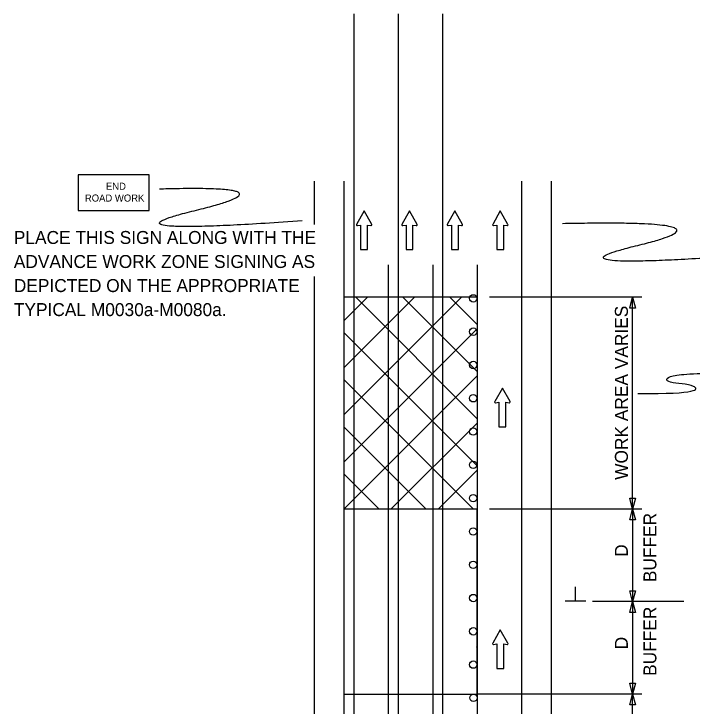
# Model space of a CAD drawing. Extents: x 16727 to 18475, y 5704 to 7011.
# Drawn here: x 16733.5 to 17100, y 6636.8 to 7011.1 of the extents above; entities that cross this region are included whole.
import ezdxf

# ---------------------------------------------------------------- set-up
doc = ezdxf.new("R2010")
doc.units = 0
for name, color, linetype in [('ALI_LEGAL_EX', 7, 'Continuous'), ('MT_SCRATCH_LEVEL_A', 7, 'Continuous'), ('MT_SCRATCH_LEVEL_E', 7, 'Continuous'), ('PAVT_EDGE_EX', 7, 'Continuous'), ('TRAFFIC_SIGNS_PR', 7, 'Continuous'), ('TYPICAL_TEXT_DIMEN_PR', 7, 'Continuous')]:
    doc.layers.add(name, color=color, linetype=linetype)

msp = doc.modelspace()

# ---------------------------------------------------------------- linework, layer by layer
at = {"layer": 'ALI_LEGAL_EX'}
for p, q in [((16917.23, 7011.11), (16917.23, 6181.92)), ((16941.23, 7011.11), (16941.23, 6181.92)), ((16965.23, 7011.11), (16965.23, 6181.92)), ((16965.23, 7011.11), (16965.23, 6181.92)), ((16935.85, 6875.49), (16935.85, 6046.3)), ((16959.85, 6875.49), (16959.85, 6046.3)), ((16983.85, 6875.49), (16983.85, 6046.3)), ((16983.85, 6875.49), (16983.85, 6046.3))]:
    msp.add_line(p, q, dxfattribs=at)
for points in [[(16935.85, 6875.49), (16935.85, 6850.49)], [(16959.85, 6875.49), (16959.85, 6850.49)], [(16983.85, 6875.49), (16983.85, 6850.49)], [(16935.85, 6775.49), (16935.85, 6750.49)], [(16959.85, 6775.49), (16959.85, 6750.49)], [(16983.85, 6775.49), (16983.85, 6750.49)], [(16935.85, 6675.49), (16935.85, 6650.49)], [(16959.85, 6675.49), (16959.85, 6650.49)], [(16983.85, 6675.49), (16983.85, 6650.49)]]:
    msp.add_lwpolyline(points, dxfattribs=at)
at = {"layer": 'MT_SCRATCH_LEVEL_A'}
for p, q in [((16911.85, 6845.15), (16924.57, 6857.87)), ((16911.85, 6819.7), (16950.02, 6857.87)), ((16911.85, 6794.24), (16975.48, 6857.87)), ((16983.85, 6857.87), (16911.85, 6857.87)), ((16983.85, 6792.25), (16918.23, 6857.87)), ((16983.85, 6817.7), (16943.69, 6857.87)), ((16983.85, 6843.16), (16969.15, 6857.87)), ((16911.85, 6768.79), (16983.85, 6840.79)), ((16983.85, 6766.79), (16911.85, 6838.79)), ((16911.85, 6743.33), (16983.85, 6815.33)), ((16981.86, 6743.33), (16911.85, 6813.34)), ((16937.31, 6743.33), (16983.85, 6789.88)), ((16956.4, 6743.33), (16911.85, 6787.88)), ((16911.85, 6787.3), (16911.85, 6643.33)), ((16911.85, 6787.3), (16911.85, 6672.76)), ((16962.77, 6743.33), (16983.85, 6764.42)), ((16930.95, 6743.33), (16911.85, 6762.42)), ((16983.85, 6743.33), (16911.85, 6743.33)), ((16911.85, 6672.76), (16911.85, 6643.33)), ((16983.76, 6671.57), (16983.81, 6671.49)), ((16983.56, 6668.93), (16983.57, 6668.81))]:
    msp.add_line(p, q, dxfattribs=at)
at = {"layer": 'MT_SCRATCH_LEVEL_E'}
for p, q in [((16922.76, 6904.53), (16918.65, 6897.29)), ((16922.76, 6904.53), (16918.65, 6897.29)), ((16926.91, 6897.29), (16922.76, 6904.53)), ((16926.91, 6897.29), (16922.76, 6904.53)), ((16947.29, 6904.53), (16943.18, 6897.29)), ((16947.29, 6904.53), (16943.18, 6897.29)), ((16951.44, 6897.29), (16947.29, 6904.53)), ((16951.44, 6897.29), (16947.29, 6904.53)), ((16971.82, 6904.53), (16967.71, 6897.29)), ((16971.82, 6904.53), (16967.71, 6897.29)), ((16975.97, 6897.29), (16971.82, 6904.53)), ((16975.97, 6897.29), (16971.82, 6904.53)), ((16996.38, 6904.53), (16992.27, 6897.29)), ((16996.38, 6904.53), (16992.27, 6897.29)), ((17000.53, 6897.29), (16996.38, 6904.53)), ((17000.53, 6897.29), (16996.38, 6904.53)), ((16919.14, 6896.61), (16920.91, 6896.93)), ((16919.14, 6896.61), (16920.91, 6896.93)), ((16920.91, 6896.93), (16920.91, 6883.67)), ((16920.91, 6896.93), (16920.91, 6883.67)), ((16924.65, 6883.67), (16924.65, 6896.93)), ((16924.65, 6896.93), (16926.43, 6896.61)), ((16924.65, 6883.67), (16924.65, 6896.93)), ((16924.65, 6896.93), (16926.43, 6896.61)), ((16943.67, 6896.61), (16945.44, 6896.93)), ((16943.67, 6896.61), (16945.44, 6896.93)), ((16945.44, 6896.93), (16945.44, 6883.67)), ((16945.44, 6896.93), (16945.44, 6883.67)), ((16949.18, 6883.67), (16949.18, 6896.93)), ((16949.18, 6896.93), (16950.96, 6896.61)), ((16949.18, 6883.67), (16949.18, 6896.93)), ((16949.18, 6896.93), (16950.96, 6896.61)), ((16968.19, 6896.61), (16969.97, 6896.93)), ((16968.19, 6896.61), (16969.97, 6896.93)), ((16969.97, 6896.93), (16969.97, 6883.67)), ((16969.97, 6896.93), (16969.97, 6883.67)), ((16973.71, 6883.67), (16973.71, 6896.93)), ((16973.71, 6896.93), (16975.49, 6896.61)), ((16973.71, 6883.67), (16973.71, 6896.93)), ((16973.71, 6896.93), (16975.49, 6896.61)), ((16992.75, 6896.61), (16994.53, 6896.93)), ((16992.75, 6896.61), (16994.53, 6896.93)), ((16994.53, 6896.93), (16994.53, 6883.67)), ((16994.53, 6896.93), (16994.53, 6883.67)), ((16998.27, 6883.67), (16998.27, 6896.93)), ((16998.27, 6896.93), (17000.05, 6896.61)), ((16998.27, 6883.67), (16998.27, 6896.93)), ((16998.27, 6896.93), (17000.05, 6896.61)), ((16920.91, 6883.67), (16924.65, 6883.67)), ((16920.91, 6883.67), (16924.65, 6883.67)), ((16945.44, 6883.67), (16949.18, 6883.67)), ((16945.44, 6883.67), (16949.18, 6883.67)), ((16969.97, 6883.67), (16973.71, 6883.67)), ((16969.97, 6883.67), (16973.71, 6883.67)), ((16994.53, 6883.67), (16998.27, 6883.67)), ((16994.53, 6883.67), (16998.27, 6883.67)), ((16997.48, 6808.78), (16993.37, 6801.54)), ((16997.48, 6808.78), (16993.37, 6801.54)), ((17001.63, 6801.54), (16997.48, 6808.78)), ((17001.63, 6801.54), (16997.48, 6808.78)), ((16993.85, 6800.85), (16995.63, 6801.17)), ((16993.85, 6800.85), (16995.63, 6801.17)), ((16995.63, 6801.17), (16995.63, 6787.91)), ((16995.63, 6801.17), (16995.63, 6787.91)), ((16999.37, 6787.91), (16999.37, 6801.17)), ((16999.37, 6801.17), (17001.15, 6800.85)), ((16999.37, 6787.91), (16999.37, 6801.17)), ((16999.37, 6801.17), (17001.15, 6800.85)), ((16995.63, 6787.91), (16999.37, 6787.91)), ((16995.63, 6787.91), (16999.37, 6787.91)), ((16996.38, 6678.13), (16992.27, 6670.89)), ((16996.38, 6678.13), (16992.27, 6670.89)), ((17000.53, 6670.89), (16996.38, 6678.13)), ((17000.53, 6670.89), (16996.38, 6678.13)), ((16992.75, 6670.2), (16994.53, 6670.52)), ((16992.75, 6670.2), (16994.53, 6670.52)), ((16994.53, 6670.52), (16994.53, 6657.26)), ((16994.53, 6670.52), (16994.53, 6657.26)), ((16998.27, 6657.26), (16998.27, 6670.52)), ((16998.27, 6670.52), (17000.05, 6670.2)), ((16998.27, 6657.26), (16998.27, 6670.52)), ((16998.27, 6670.52), (17000.05, 6670.2)), ((16994.53, 6657.26), (16998.27, 6657.26)), ((16994.53, 6657.26), (16998.27, 6657.26))]:
    msp.add_line(p, q, dxfattribs=at)
for centre, start, end in [((16919.06, 6897.07), 150.4248, 279.9638), ((16919.06, 6897.07), 150.4248, 279.9638), ((16926.5, 6897.07), 260.0362, 29.7731), ((16926.5, 6897.07), 260.0362, 29.7731), ((16943.59, 6897.07), 150.4248, 279.9638), ((16943.59, 6897.07), 150.4248, 279.9638), ((16951.03, 6897.07), 260.0362, 29.7731), ((16951.03, 6897.07), 260.0362, 29.7731), ((16968.12, 6897.07), 150.4248, 279.9638), ((16968.12, 6897.07), 150.4248, 279.9638), ((16975.56, 6897.07), 260.0362, 29.7731), ((16975.56, 6897.07), 260.0362, 29.7731), ((16992.68, 6897.07), 150.4248, 279.9638), ((16992.68, 6897.07), 150.4248, 279.9638), ((17000.12, 6897.07), 260.0362, 29.7731), ((17000.12, 6897.07), 260.0362, 29.7731), ((16993.78, 6801.31), 150.4248, 279.9638), ((16993.78, 6801.31), 150.4248, 279.9638), ((17001.22, 6801.31), 260.0362, 29.7731), ((17001.22, 6801.31), 260.0362, 29.7731), ((16992.68, 6670.66), 150.4248, 279.9638), ((16992.68, 6670.66), 150.4248, 279.9638), ((17000.12, 6670.66), 260.0362, 29.7731), ((17000.12, 6670.66), 260.0362, 29.7731)]:
    msp.add_arc(centre, 0.463, start, end, dxfattribs=at)
at = {"layer": 'PAVT_EDGE_EX'}
for p, q in [((16895.85, 6920.73), (16895.85, 6897.26)), ((16911.85, 6920.73), (16911.85, 6024.13)), ((17007.85, 6920.73), (17007.85, 6024.13)), ((17023.85, 6920.73), (17023.85, 6024.13)), ((16895.85, 6869.12), (16895.85, 6024.13))]:
    msp.add_line(p, q, dxfattribs=at)
msp.add_lwpolyline([(16983.85, 6743.33), (16911.85, 6743.33), (16911.85, 6643.33), (16983.85, 6643.33)], close=True, dxfattribs=at)
at = {"layer": 'TRAFFIC_SIGNS_PR'}
msp.add_lwpolyline([(16768.29, 6904.86), (16806.69, 6904.86), (16806.69, 6924.06), (16768.29, 6924.06)], close=True, dxfattribs=at)
for centre in [(16981.76, 6857.28), (16981.76, 6839.28), (16981.76, 6821.28), (16981.76, 6803.28), (16981.76, 6785.28), (16981.76, 6767.28), (16981.76, 6749.28), (16981.76, 6731.28), (16981.76, 6713.28), (16981.76, 6695.28), (16981.76, 6677.28), (16981.76, 6659.28), (16981.85, 6641.33), (16981.85, 6641.33)]:
    msp.add_circle(centre, 2, dxfattribs=at)
for points in [[(16889.36, 6899.17), (16774.14, 6890.93), (16888.05, 6918.52), (16812.21, 6916.35)], [(17129.18, 6880.47), (17013.95, 6872.23), (17127.86, 6899.81), (17029.92, 6897.64)]]:
    msp.add_open_spline(points, degree=2, dxfattribs=at)
at = {"layer": 'TYPICAL_TEXT_DIMEN_PR'}
for p, q in [((17072.85, 6857.87), (16990.46, 6857.87)), ((17066.28, 6852.01), (17067.85, 6857.87)), ((17067.85, 6743.33), (17067.85, 6857.87)), ((17067.85, 6857.87), (17069.42, 6852.01)), ((17067.85, 6852.01), (17066.28, 6852.01)), ((17069.42, 6852.01), (17067.85, 6852.01)), ((17067.85, 6743.33), (17066.28, 6749.19)), ((17066.28, 6749.19), (17067.85, 6749.19)), ((17067.85, 6749.19), (17069.42, 6749.19)), ((17069.42, 6749.19), (17067.85, 6743.33)), ((17072.85, 6743.33), (16990.46, 6743.33)), ((17072.85, 6743.33), (16990.46, 6743.33)), ((17066.28, 6737.47), (17067.85, 6743.33)), ((17067.85, 6743.33), (17067.85, 6693.33)), ((17067.85, 6743.33), (17069.42, 6737.47)), ((17067.85, 6737.47), (17066.28, 6737.47)), ((17069.42, 6737.47), (17067.85, 6737.47)), ((17036.98, 6693.52), (17036.98, 6701.31)), ((17067.85, 6693.33), (17066.28, 6699.19)), ((17066.28, 6699.19), (17067.85, 6699.19)), ((17067.85, 6699.19), (17069.42, 6699.19)), ((17069.42, 6699.19), (17067.85, 6693.33)), ((17042.6, 6693.52), (17031.35, 6693.52)), ((17095.51, 6693.33), (17046.27, 6693.33)), ((17066.28, 6687.47), (17067.85, 6693.33)), ((17067.85, 6693.33), (17067.85, 6643.33)), ((17067.85, 6693.33), (17069.42, 6687.47)), ((17067.85, 6687.47), (17066.28, 6687.47)), ((17069.42, 6687.47), (17067.85, 6687.47)), ((17067.85, 6643.33), (17066.28, 6649.19)), ((17066.28, 6649.19), (17067.85, 6649.19)), ((17067.85, 6649.19), (17069.42, 6649.19)), ((17069.42, 6649.19), (17067.85, 6643.33)), ((17072.85, 6643.33), (16983.85, 6643.33)), ((17066.28, 6637.47), (17067.85, 6643.33)), ((17067.85, 6612.77), (17067.85, 6643.33)), ((17067.85, 6643.33), (17069.42, 6637.47)), ((17067.85, 6637.47), (17066.28, 6637.47)), ((17069.42, 6637.47), (17067.85, 6637.47))]:
    msp.add_line(p, q, dxfattribs=at)
msp.add_open_spline([(17070.66, 6805.93), (17103.88, 6805.42), (17103.88, 6811.13), (17085.32, 6811.13), (17085.32, 6815.94), (17103.5, 6816.88), (17122.14, 6816.84)], degree=3, dxfattribs=at)

# ---------------------------------------------------------------- texts
at = {"layer": 'TRAFFIC_SIGNS_PR'}
for s, height, p in [('END', 3.831, (16783.29, 6915.99)), ('ROAD WORK', 3.831, (16771.9, 6909.61)), ('PLACE THIS SIGN ALONG WITH THE', 7, (16733.52, 6886.71)), ('ADVANCE WORK ZONE SIGNING AS', 7, (16733.52, 6873.71)), ('DEPICTED ON THE APPROPRIATE', 7, (16733.52, 6860.71)), ('TYPICAL M0030a-M0080a.', 7, (16733.52, 6847.71))]:
    msp.add_text(s, height=height, dxfattribs=at).set_placement(p)
at = {"layer": 'TYPICAL_TEXT_DIMEN_PR'}
for s, p in [('WORK AREA VARIES', (17065.3, 6759.18)), ('BUFFER', (17080.72, 6703.88)), ('D', (17065.3, 6717.55)), ('BUFFER', (17080.72, 6653.19)), ('D', (17065.3, 6667.55))]:
    msp.add_text(s, height=7, rotation=90, dxfattribs=at).set_placement(p)

doc.saveas('drawing.dxf')
